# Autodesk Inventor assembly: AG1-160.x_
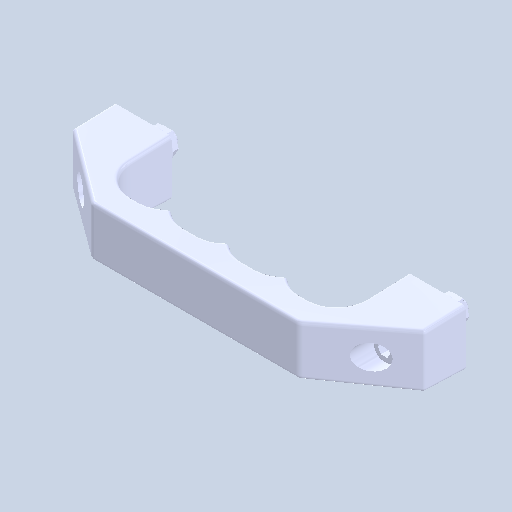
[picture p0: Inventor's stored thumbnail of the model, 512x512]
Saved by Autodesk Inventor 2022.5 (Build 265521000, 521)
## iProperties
Created: 2024-05
Part Number: AG1-160.x_
Document SubType Name: Assembly
Designer: ImaoCorp
Author: ImaoCorp
Sending System: SOLIDWORKS 2022-2022290
MC: AMD64
MC_MODEL: Intel64 Family 6 Model 60 Stepping 3, GenuineIntel
OS: Windows_NT
FRU: Parasolid Version 33.1, build 260,  4-25-2022
FORMAT: text
GUISE: transmit
KEY: FILEAG1-160.x_t
DATE: Fri May 31 16:17:41 2024
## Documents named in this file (4)
- Y:\5.更新分\2024年対応\0530_ROHDE\ag1\ag1-160\AG1-160.x_.iam
- Y:\5.更新分\2024年対応\0530_ROHDE\ag1\ag1-160\AG1-160_01.ipt
- Y:\5.更新分\2024年対応\0530_ROHDE\ag1\ag1-160\AG1-160_02.ipt
- Y:\5.更新分\2024年対応\0530_ROHDE\ag1\ag1-160\AG1-160_03.ipt
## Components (3 placed, 3 different names)
1. AG1-160_01
2. AG1-160_02
3. AG1-160_03
